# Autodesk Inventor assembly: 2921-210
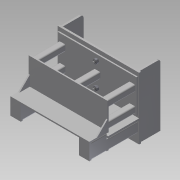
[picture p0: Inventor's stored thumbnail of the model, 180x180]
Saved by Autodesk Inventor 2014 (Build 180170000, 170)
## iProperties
Company: NHTSA/VRTC
Created: 2012-08
Part Number: 2921-210
Document SubType Name: Assembly
Designer: Mike Vanvoorhis
Mass: 34454.8 g
Surface Area: 13341.2 cm^2
Volume: 4383.57 cm^3
Density: 7.86 g/cm^3
Description: IMPACTOR STOP ASSEMBLY
Project: CHILD SIDE IMPACT SLED
Author: Dave Walker
Title: Impactor Stop Assembly
Subject: Child Side Impact Sled
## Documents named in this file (5)
- B:\VRTC_DWG\BIO\Non-P572\Child Side-Frontal Impact Sled\Side Impact Sled\Impactor_Frame_Assembly_2.iam
- B:\VRTC_DWG\BIO\Non-P572\Child Side-Frontal Impact Sled\Side Impact Sled\Impactor_Frame_Assembly.iam
- B:\VRTC_DWG\BIO\Non-P572\Child Side-Frontal Impact Sled\Side Impact Sled\Honeycomb_Fixture_Assembly.iam
- B:\VRTC_DWG\Inventor Support Files\Content Center\en-US\ASME B18.21.1(10)\ASME B18.21.1 - 1_2(2).ipt
- B:\VRTC_DWG\Inventor Support Files\Content Center\en-US\ANSI ASME B18.2.1(2)\ANSI_ASME B18.2.1 - 1_2-13 UNC - 1.5(2).ipt
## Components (6 placed, 4 different names)
1. Impactor_Frame_Assembly:1 [sub-assembly] — Flush:1, Mate:1, Flush:2, Insert:1, Insert:2
2. Honeycomb_Fixture_Assembly:1 [sub-assembly] — Flush:1, Mate:1, Flush:2, Flush:3
3. Regular Helical Spring Lock Washer (Inch) 1/2:1 — Insert:1, Insert:3
4. Regular Helical Spring Lock Washer (Inch) 1/2:2 — Insert:2, Insert:4
5. Hex Bolt - Inch 1/2-13 UNC - 1.5:1 — Insert:3
6. Hex Bolt - Inch 1/2-13 UNC - 1.5:2 — Insert:4
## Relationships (8: Insert 4, Flush 3, Mate 1)
- Flush:1: Impactor_Frame_Assembly:1 ↔ Honeycomb_Fixture_Assembly:1
- Mate:1: Impactor_Frame_Assembly:1 ↔ Honeycomb_Fixture_Assembly:1
- Flush:2: Impactor_Frame_Assembly:1 ↔ Honeycomb_Fixture_Assembly:1
- Insert:1: Impactor_Frame_Assembly:1 ↔ Regular Helical Spring Lock Washer (Inch) 1/2:1
- Insert:2: Impactor_Frame_Assembly:1 ↔ Regular Helical Spring Lock Washer (Inch) 1/2:2
- Insert:3: Regular Helical Spring Lock Washer (Inch) 1/2:1 ↔ Hex Bolt - Inch 1/2-13 UNC - 1.5:1
- Insert:4: Regular Helical Spring Lock Washer (Inch) 1/2:2 ↔ Hex Bolt - Inch 1/2-13 UNC - 1.5:2
- Flush:3: Honeycomb_Fixture_Assembly:1
